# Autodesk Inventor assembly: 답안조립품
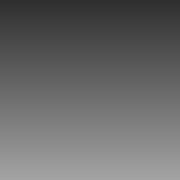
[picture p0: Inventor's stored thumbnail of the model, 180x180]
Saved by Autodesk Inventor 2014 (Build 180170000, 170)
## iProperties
Created: 2016-05
Part Number: 답안조립품
Document SubType Name: Assembly
Designer: Administrator
Author: Administrator
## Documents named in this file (1)
- C:\Users\Administrator\Desktop\460507V1014\답안조립품.iam
